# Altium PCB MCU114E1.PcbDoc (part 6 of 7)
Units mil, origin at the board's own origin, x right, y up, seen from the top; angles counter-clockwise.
Board outline 4163.97 x 2322.49 mil, 8 copper layers (Top Layer, GND 2, Signal Layer 3, Power 4, Power 5, Signal Layer 6, GND 7, Bottom), stack 61.2 mil thick; 444 components, 416 nets, 1812 pads, 989 vias.
Unrouted connection lines stored in the file: 3.
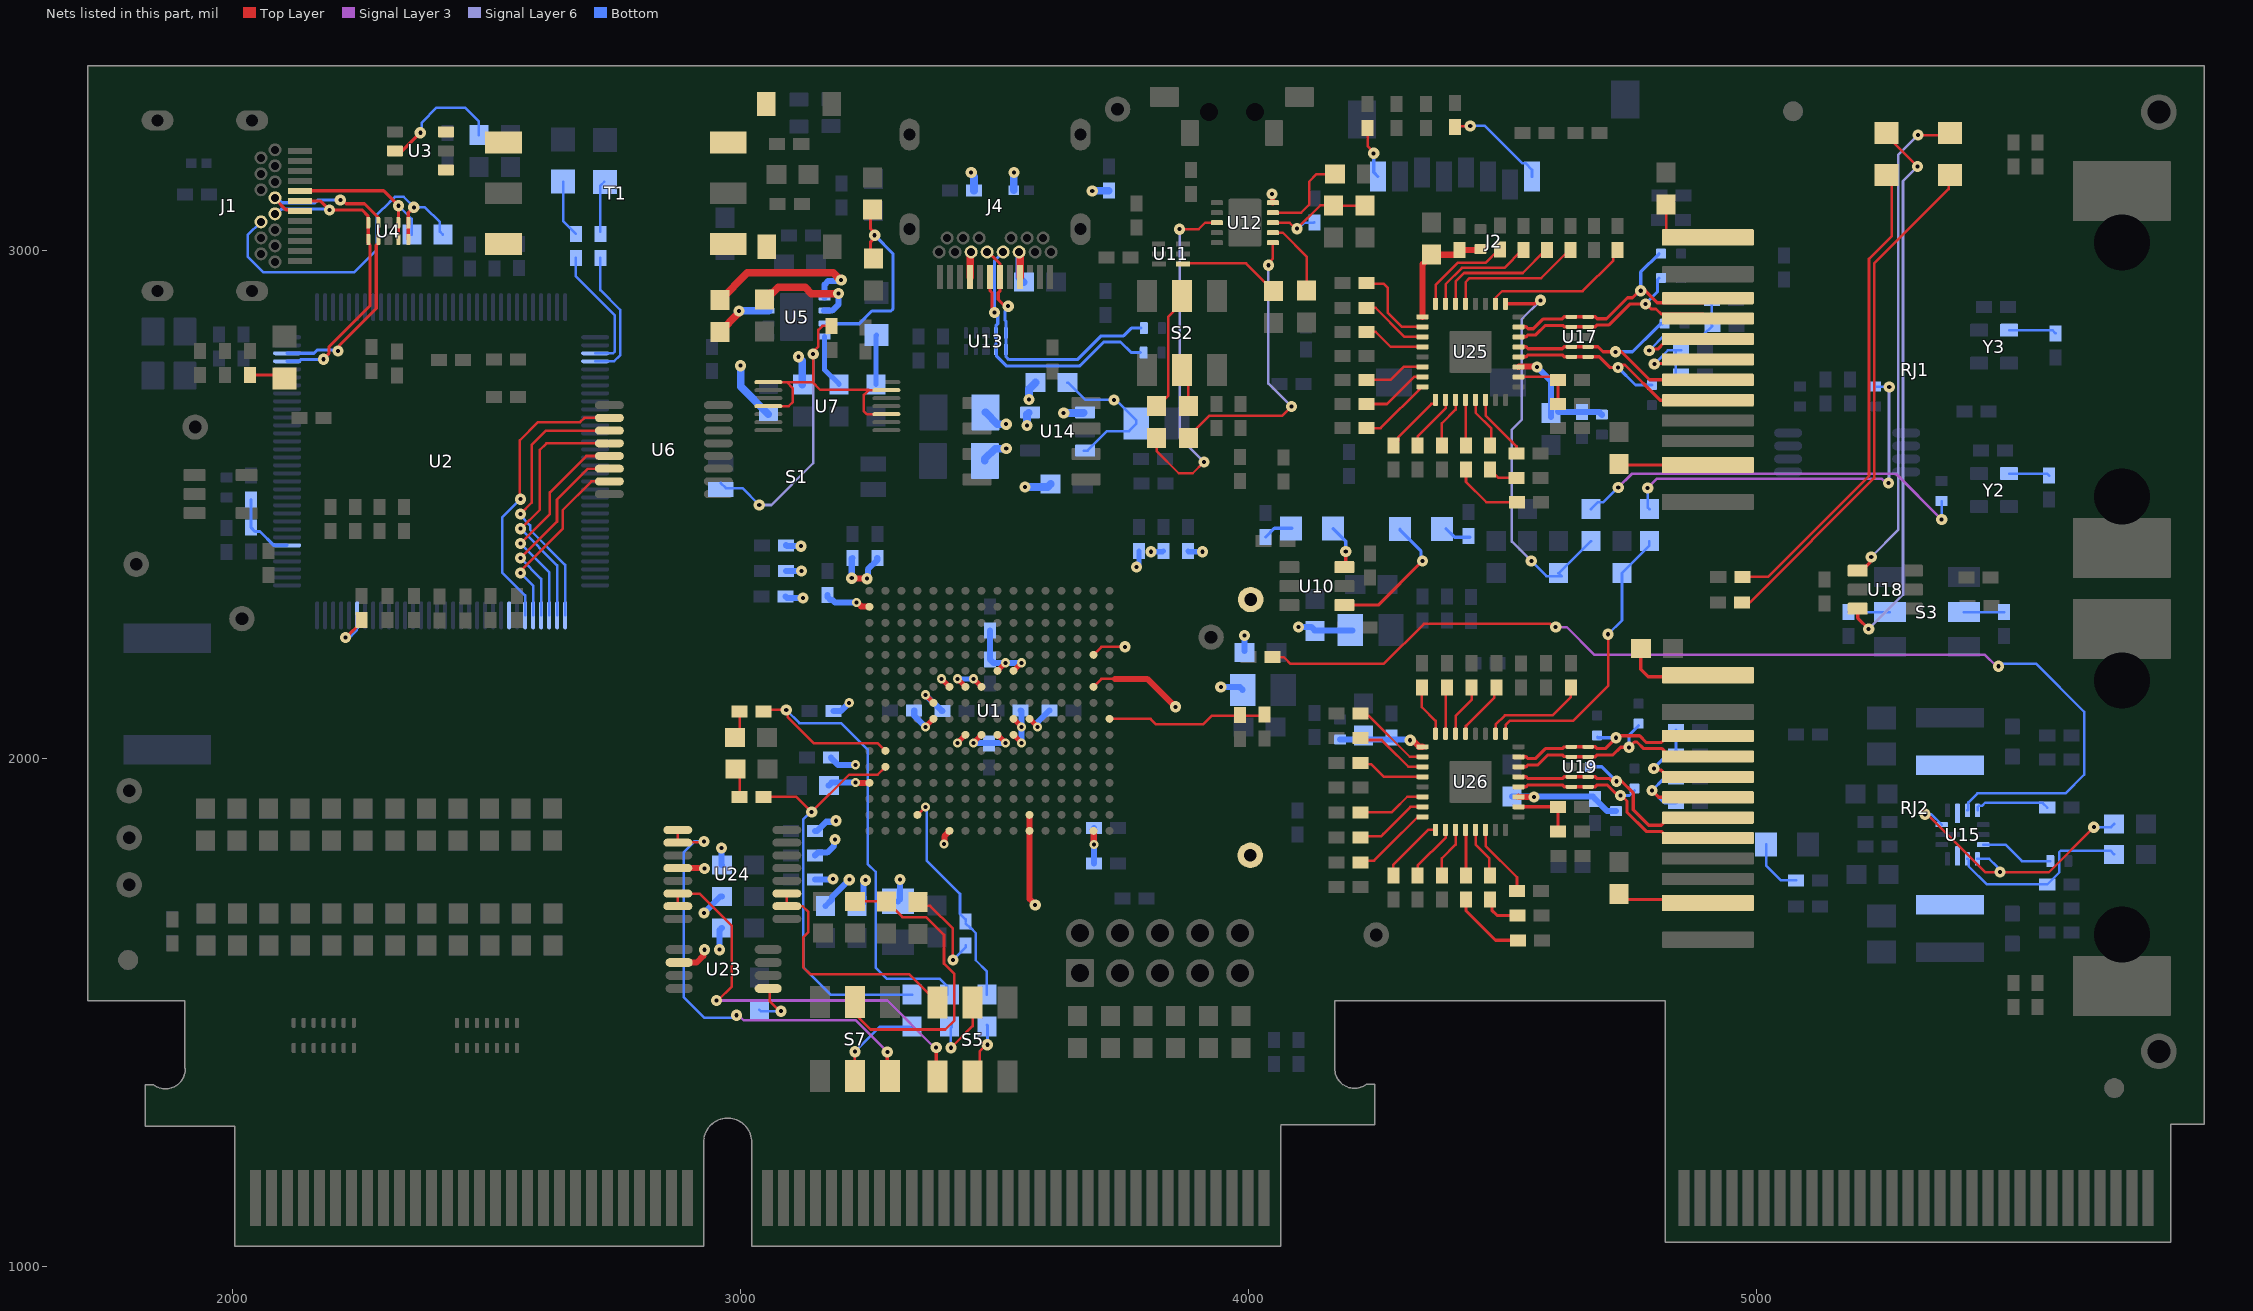
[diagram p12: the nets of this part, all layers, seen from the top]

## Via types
v1: diameter 22, hole 8, Top Layer to Bottom, tented both sides, 818 vias
v2: diameter 18, hole 8, Top Layer to Bottom, tented both sides, 153 vias
v3: diameter 19.68, hole 7.87, Top Layer to Bottom, 18 vias

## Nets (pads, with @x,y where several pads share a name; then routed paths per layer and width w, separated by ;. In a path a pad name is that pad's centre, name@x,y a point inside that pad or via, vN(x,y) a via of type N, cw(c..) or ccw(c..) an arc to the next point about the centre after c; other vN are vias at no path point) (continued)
NetC63_1: C63.1 R198.1 | length 58.3
  Top Layer w5: C63.1@2990.34,1980.27 2998.21,1972.39 R198.1@2998.21,1925.27
NetC87_2: C87.2 C88.2 RJ1.5 | length 321
  Top Layer w6.25: v1(4788,2803) 4791.01,2806.01 4804.85,2806.01 4817.8,2818.96 4896.34,2818.96 RJ1.5@4903.31,2825.92
  Bottom w5: v1(4788,2803) 4819.35,2834.35 4894.89,2834.35 C88.2@4912.38,2851.84 4911.38,2852.84 C87.2@4911.38,2903
NetC89_1: C89.1 C90.1 U25.2 | length 168.8
  Top Layer w5: U25.2@4530.92,2751.47 4601.11,2751.47 C90.1@4608.21,2744.37 ; C90.1@4608.21,2745.27 C90.1@4608.21,2744.37 ; C89.1@4608.81,2697.86 4608.21,2698.47 C90.1@4608.21,2744.37 ; C89.1@4608.81,2703.69 4608.81,2743.77 C90.1@4608.21,2744.37
NetC95_2: C95.2 C96.2 RJ1.6 | length 217.6
  Top Layer w6.25: v1(4798,2777) 4798.9,2777.9 4895.44,2777.9 RJ1.6@4903.31,2785.76
  Bottom w5: v1(4798,2777) 4824.45,2803.45 C96.2@4840.44,2803.45 ; C95.2@4840.44,2758.69 C96.2@4840.44,2803.45 ; C96.2@4850.99,2803.45 C96.2@4840.44,2803.45
NetC97_1: C97.1 C98.1 R131.2 U25.3 | length 235.7
  Top Layer w12: U25.3@4530.92,2771.16 4531.45,2771.69 v1@4567.44,2771.69
  Bottom w12: v1(4567,2771) 4595.08,2742.92 C97.1@4595.08,2672.42 ; C97.1@4608.66,2683.2 4609.66,2682.2 C98.1@4655.66,2682.2 4689.58,2682.2 R131.2@4694.83,2676.95
NetC99_1: C99.1 C100.1 R134.1 U25.17 | length 228.9
  Top Layer w12: U25.17@4341.95,2869.58 4341.95,2972.9 4359.83,2990.79 C99.1@4359.83,2991.77 4409.02,2991.77 4414.83,2997.58 C100.1@4414.83,3000.65 4448.05,3000.65 R134.1@4451.99,3004.58
NetC102_2: C102.2 C104.2 RJ2.5 | length 234.3
  Top Layer w6.25: v1(4797,1981) 4800.01,1977.99 4811.04,1977.99 4824.76,1964.27 RJ2.5@4921.83,1964.27
  Bottom w6.25: v1(4797,1981) 4815.86,1999.86 4831.75,1999.86 C104.2@4840.44,2008.54 C102.2@4840.44,2056.26
NetC105_1: C105.1 C106.1 U26.2 | length 125.7
  Top Layer w6.1: U26.2@4530.92,1905.47 C106.1@4608.81,1905.47 C105.1@4608.81,1857.69
NetC111_2: C111.2 C112.2 RJ2.6 | length 247.7
  Top Layer w6.25: v1(4793.44,1937.5) 4806.83,1924.11 RJ2.6@4921.83,1924.11
  Bottom w6.25: C112.2@4840.44,1913.11 4817.83,1913.11 v1(4793.44,1937.5) 4816.76,1960.83 C111.2@4840.44,1960.83
NetC113_1: C113.1 C114.2 R166.2 U26.3 | length 247.4
  Top Layer w12: U26.3@4530.92,1925.16 4531.4,1924.69 v1(4561.44,1924.69)
  Bottom w12: C113.1@4518,1925.5 4676.95,1925.5 C114.2@4681.65,1920.81 4705.5,1896.95 R166.2@4722.83,1896.95
NetC115_1: C115.1 C116.2 R168.1 U26.17 | length 167.8
  Top Layer w12: v1(4317.67,2036.43) 4320.68,2033.42 4325.22,2033.42 4335.06,2023.58 U26.17@4341.95,2023.58
  Bottom w12: R168.1@4179.99,2037.69 4316.41,2037.69 v1(4317.67,2036.43)
NetC118_1: C118.1 R199.1 | length 190.4
  Top Layer w5: C118.1@3349.59,1718.01 3356.97,1710.63 3372.87,1710.63 3417.83,1665.67 v1(3417.83,1604.27)
  Bottom w5: v1(3417.83,1604.27) 3418.39,1604.27 3442.83,1628.71 R199.1@3442.83,1632.65
NetC119_1: C119.1 R200.1 | length 53.6
  Top Layer w5: C119.1@2990.34,2042.27 2998.21,2050.14 R200.1@2998.21,2092.56
NetC121_1: C121.1 U23.5 | length 104.2
  Top Layer w5: U23.5@3057.19,1552.13 3057.19,1522.91 3076.83,1503.27 v1(3079.83,1503.27)
  Bottom w5: C121.1@3036.87,1506.19 3039.79,1503.27 v1(3079.83,1503.27)
NetC122_1: C122.1 R57.1 S7.5 | length 620.1
  Top Layer w5: R57.1@3225.09,1718.52 R57.1@3225.09,1719.51 3288.1,1719.51 C122.1@3287.59,1719.01 3318.33,1688.27 3365.33,1688.27 3400.33,1653.27 3400.33,1597.02 3420.83,1576.52 3420.83,1485.27 3402.83,1467.27 3256.12,1467.27 3225.59,1497.8 S7.5@3225.59,1521.35
NetD2_2: D2.2 R14.2 | length 70.8
  Top Layer w5: R14.2@2034.87,2755.06 2096.16,2755.06 D2.2@2102.87,2748.35
NetD3_2: D3.2 T1.1
NetD4_2: D4.2 T1.3
NetD5_1: D5.1 U10.6 | length 86.2
  Top Layer w6.25: U10.6@4190.87,2376.69 v1(4190.87,2407.69)
  Bottom w6.25: D5.1@4166.21,2452.69 4190.87,2428.02 v1(4190.87,2407.69)
NetD5_2: D5.2 R34.2 | length 59.3
  Bottom w6.25: R34.2@4032.87,2436.06 4050.49,2453.69 D5.2@4084.87,2453.69
NetD6_1: D6.1 U10.4 | length 271.2
  Top Layer w6.25: U10.4@4188.01,2302.28 4254.85,2302.28 v1(4341.83,2389.27)
  Bottom w6.25: D6.1@4297.49,2452.27 4297.49,2450.3 4338.82,2408.98 4338.82,2392.28 v1(4341.83,2389.27)
NetD6_2: D6.2 R35.2 | length 53.7
  Bottom w6.25: D6.2@4388.21,2452.69 4405.21,2435.69 R35.2@4434.87,2435.69
NetD7_2: D7.2 R21.1 | length 97.3
  Bottom w10: R21.1@3266.55,2736.5 3266.55,2832.24 D7.2@3267.62,2833.31
NetD8_1: D8.1 R8.1 | length 113.1
  Bottom w5: D8.1@2650.87,3135.35 2650.87,3057.91 R8.1@2676.09,3032.69
NetD9_2: D9.2 R94.1 | length 112.9
  Bottom w5: D9.2@5018.1,1831.69 5018.1,1790.02 5047.44,1760.69 R94.1@5077.15,1760.69
NetD11_1: D11.1 U18.6 | length 1090.3
  Top Layer w6.25: U18.6@5198.3,2295.28 5198.3,2276.8 v1(5219.83,2255.27) ; D11.1@5254.83,3231.61 5254.83,3226.27 v1(5315.83,3165.27)
  Signal Layer 6 w5: v1(5219.83,2255.27) 5287.33,2322.77 5287.33,3136.77 v1(5315.83,3165.27)
NetD11_2: D11.2 R137.1 | length 946.9
  Top Layer w5: R137.1@4971.06,2357.69 5021.75,2357.69 5220.44,2556.37 5220.44,2983.44 5265,3028 5265,3138.76 D11.2@5254.83,3148.93
NetD12_1: D12.1 U18.4 | length 975.1
  Top Layer w5: v1(5316.83,3227.27) 5375.68,3227.27 D12.1@5379.44,3231.02
  Top Layer w6.25: U18.4@5198.3,2370.09 5206.18,2370.09 5221.82,2385.73 5221.82,2394.25 v1(5224.83,2397.27)
  Signal Layer 6 w5: v1(5224.83,2397.27) 5278.33,2450.77 5278.33,3188.77 v1(5316.83,3227.27)
NetD12_2: D12.2 R138.2 | length 1019.3
  Top Layer w5: R138.2@4970.49,2307.69 4986.25,2307.69 5230.69,2552.12 5230.69,2974.69 5376.98,3120.98 5376.98,3145.89 D12.2@5379.44,3148.35
NetD13_1: D13.1 R9.1 | length 101.9
  Bottom w5: R9.1@2724.09,3036.63 2724.09,3127.57 D13.1@2731.87,3135.35
NetJ2_1: J2.1 R37.1 | length 201.7
  Top Layer w5: R37.1@4405.83,3242.65 4408.04,3244.85 v1(4435.79,3244.85)
  Bottom w5: v1(4435.79,3244.85) 4436.21,3245.27 4464.56,3245.27 4537.96,3171.87 4544.12,3171.87 4557.37,3158.62 J2.1@4557.37,3145.39
NetJ2_8: J2.8 R43.2 | length 104.1
  Top Layer w5: R43.2@4233.87,3241.06 4233.87,3205.47 4245.83,3193.51 v1(4245.83,3191.27)
  Bottom w6.25: v1(4245.83,3191.27) 4245.83,3153.78 J2.8@4254.22,3145.39
NetL1_1: L1.1 U15.6
NetL2_1: L2.1 U15.12
NetR1_1: R1.1 S1.1 U7.1 U7.4 U7.10 U7.13 | length 1012
  Top Layer w5: U7.4@3054.73,2693.69 3094.87,2693.69 3102.87,2701.69 3102.87,2728.93 3090.87,2740.93 ; U7.1@3054.73,2740.93 3090.87,2740.93 ; 3142.99,2739.56 3142.99,2800.81 3153,2810.81 3153,2843.81 3160.87,2851.69 R1.1@3178.87,2851.69 ; 3252.37,2725.69 3156.87,2725.69 3141.63,2740.93 3090.87,2740.93 ; U7.13@3287.01,2725.18 3252.37,2725.18 3242.87,2715.69 3242.87,2683.69 3248.87,2677.69 U7.10@3288.87,2677.69
  Signal Layer 6 w5: v1(3036.83,2499.27) 3060.73,2499.27 3142.87,2581.41 v1@3142.87,2793.69
  Bottom w5: S1.1@2960.87,2542.69 2971.15,2532.41 3003.69,2532.41 v1(3036.83,2499.27)
  other v1: 3142.99,2796.21
NetR8_2: R8.2 U2.3 | length 255.9
  Bottom w5: R8.2@2676.09,2985.44 2676.09,2949.07 2752.69,2872.48 2752.69,2801.52 2749.02,2797.86 U2.3@2714,2797.86
NetR9_2: R9.2 U2.4 | length 261.5
  Bottom w5: U2.4@2714,2782.11 2751.3,2782.11 2762.87,2793.69 2762.87,2883.48 2724.09,2922.26 R9.2@2724.09,2985.44
NetR10_1: R10.1 R11.2 U2.70 | length 140.6
  Bottom w6.25: R10.1@2036.87,2510.06 R11.2@2036.87,2454.69 2044.4,2447.16 2054.4,2447.16 2081.34,2420.21 2107.39,2420.21 U2.70@2107.7,2419.9
NetR12_2: R12.2 U2.59 | length 105.5
  Top Layer w6.25: v1(2222.83,2238.27) 2223.48,2238.27 2254.09,2268.89 R12.2@2254.09,2272.82
  Bottom w5: v1(2222.83,2238.27) 2226.08,2241.52 2233.65,2241.52 2244.97,2252.84 2244.97,2281.58 U2.59@2245.49,2282.11
NetR18_1: R18.1 U3.5 | length 248.7
  Top Layer w6.25: U3.5@2319.9,3196.07 2334.25,3196.07 v1(2369.87,3231.69)
  Bottom w5: v1(2369.87,3231.69) 2372.89,3234.7 2372.89,3251.86 2402.03,3281 2458.16,3281 2485.09,3254.07 R18.1@2485.09,3226.94
NetR19_1: R19.1 U5.1 | length 327.9
  Top Layer w15: R19.1@2960,2902.5 3013.5,2956 3182.11,2956 3196.11,2942 v1(3198,2942)
  Bottom w12: U5.1@3165.45,2907.38 3165.45,2933.06 3172.48,2940.09 3196.09,2940.09 v1(3198,2942)
NetR24_1: R24.1 R26.2 U5.3 | length 405
  Top Layer w6.25: R24.1@3253.87,3077.19 3255.87,3075.19 3255.87,3042.39 3264,3034.26 3264,3025.74 3255.87,3017.61 R26.2@3255.87,2981.69
  Bottom w6.25: U5.3@3169.9,2856.09 3233.63,2856.09 3258.55,2881 3296.16,2881 3299.82,2884.66 3299.82,2994.18 v1(3264,3030)
NetR25_2: R25.2 U5.4 | length 106.5
  Bottom w10: U5.4@3165.45,2830.61 3165.45,2765.04 3179.31,2751.18 3180.29,2751.18 3193.99,2737.48 R25.2@3193.99,2736.5
NetR27_2: R27.2 U5.2 | length 217.6
  Top Layer w15: R27.2@3050.87,2901.17 3050.87,2908.64 3058,2915.76 3062.02,2915.76 3073.99,2927.74 3126.9,2927.74 3139.37,2915.27 v1(3192.83,2915.27)
  Bottom w12: U5.2@3163.99,2881.68 3180.24,2881.68 3192.83,2894.27 v1(3192.83,2915.27)
NetR33_1: R33.1 S2.2 | length 237.8
  Top Layer w5: R33.1@3820.44,2693.2 3841.81,2714.58 3841.81,2869.81 3851.81,2879.81 3851.81,2893.65 S2.2@3869,2910.83
NetR33_2: R33.2 U12.3 | length 702.6
  Top Layer w5: R33.2@3818.8,2630.9 3818.8,2605.18 3862.21,2561.77 3889.77,2561.77 v1(3912,2584) ; v1(3864,3042) 3901.61,3042 3914.29,3054.69 U12.3@3937.32,3054.69
  Signal Layer 6 w5: v1(3864,3042) 3864,2632 v1(3912,2584)
NetR44_2: R44.2 U11.4 | length 202
  Top Layer w5: U11.4@3870.41,2973.58 3870.41,2974.77 3994.83,2974.77 R44.2@4048.83,2920.76
NetR46_2: R46.2 R48.1 U1.J16 | length 317.2
  Top Layer w5: U1.J16@3726.04,2078.54 3806.73,2078.54 3817.52,2067.75 3910.17,2067.75 3927.33,2084.91 4029.29,2084.91 R46.2@4031,2086.62
NetR49_2: R49.2 U12.9 | length 179.7
  Top Layer w5: U12.9@4047.55,3074.37 4102.83,3074.37 4119,3090.54 4119,3135.77 4133.5,3150.27 R49.2@4169.34,3150.27
NetR52_1: R52.1 U12.6 | length 574.3
  Top Layer w5: R52.1@3881.87,2631.19 3881.87,2634.23 3922.64,2675 4066,2675 v1(4084,2693) ; v1(4039,2971) 4039,2975.6 4047.55,2984.15 U12.6@4047.55,3015.32
  Signal Layer 6 w5: v1(4039,2971) 4038.71,2970.71 4038.71,2738.29 v1(4084,2693)
NetR52_2: R52.2 S2.5 | length 75.6
  Top Layer w5: S2.5@3869,2765.17 3881,2753.17 R52.2@3881,2694.5
NetR53_1: R53.1 U15.4 U15.10 | length 567
  Top Layer w5: v1@5324.44,1890.69 v1(5330.83,1890.69) 5335.31,1890.69 5449.47,1776.53 5574.09,1776.53 v1(5662.83,1865.27)
  Bottom w5: v1(5330.83,1890.69) 5343.27,1890.69 U15.10@5363.59,1870.37 ; U15.4@5433.96,1802.95 5457.01,1802.95 5472.4,1787.56 5472.4,1787.2 5483.07,1776.53 v1@5483.44,1776.53 ; v1(5662.83,1865.27) 5696.61,1865.27 R53.1@5702.94,1871.6
  other v1: 5478,1777
NetR55_2: R55.2 R78.2 R194.1 U12.8 | length 245.2
  Top Layer w5: U12.8@4047.55,3054.69 4080.52,3054.69 4092.21,3043 v1(4095,3043) 4141.06,3089.06 R78.2@4166.72,3089.06 ; R78.2@4168.13,3087.76 R55.2@4231.13,3087.76
  Bottom w5: v1(4095,3043) 4097.79,3043 4109.48,3054.69 4128.31,3054.69 R194.1@4129,3055.38
NetR58_1: R58.1 U25.23 | length 132
  Top Layer w5: R58.1@4232.06,2698.02 4271.77,2698.02 4325.22,2751.47 U25.23@4341.95,2751.47
NetR61_1: R61.1 S5.5 | length 114.4
  Top Layer w5: S5.5@3456.59,1374.68 3470.58,1388.67 3470.58,1424.02 v1@3484.83,1438.27
  Bottom w6.1: R61.1@3484.83,1476.07 3485.58,1475.32 v1(3485.58,1437.27)
NetR61_2: R61.2 R199.2 U1.R4 | length 438.6
  Top Layer w5: U1.R4@3348.09,1889.56 v2(3363.83,1905.31)
  Bottom w5: v2(3363.83,1905.31) 3366.08,1903.06 3366.08,1800.02 3431.83,1734.27 3431.83,1694.83 3442.83,1683.83 R199.2@3442.83,1679.89 ; R199.2@3442.83,1675.95 3452.14,1666.64 3453.15,1666.64 3462.83,1656.96 3462.83,1607.06 3462.83,1603.54 3484.83,1581.54 R61.2@3484.83,1535.76
NetR62_2: R62.2 S3.2 | length 79.2
  Bottom w5: S3.2@5407.27,2288.69 R62.2@5486.44,2288.69
NetR63_2: R63.2 S3.5 | length 81.2
  Bottom w5: R63.2@5180.44,2288.69 S3.5@5261.6,2288.69
NetR69_2: R69.2 Y2.1 | length 80.3
  Bottom w5: Y2.1@5496.13,2561.17 5570.93,2561.17 R69.2@5574.83,2557.27
NetR76_2: R76.2 Y3.1 | length 94.3
  Bottom w5: Y3.1@5496.13,2843.17 5581.56,2843.17 R76.2@5587.83,2836.89
NetR82_2: R82.2 U15.13 | length 2102.6
  Top Layer w5: R82.2@4046.45,2200 4068.91,2200 4082.41,2186.5 4265.5,2186.5 4344.5,2265.5 4592.9,2265.5 4599.4,2259 v1(4604,2259)
  Signal Layer 3 w5: v1(4604,2259) 4625.75,2259 4679.75,2205 4956.35,2205 4956.58,2204.77 4971.08,2204.77 4971.31,2205 5448,2205 5471,2182 v1(5475,2182)
  Bottom w5: U15.13@5414.28,1898.42 5416.05,1900.19 5416.05,1914.31 5433.74,1932 5607,1932 5644.03,1969.03 5644.03,2091.97 5548.69,2187.31 5484.91,2187.31 5479.6,2182 v1(5475,2182)
NetR83_1: R83.1 U25.27 | length 101.1
  Top Layer w5: R83.1@4379.8,2616.31 4379.8,2659.8 4406.91,2686.91 U25.27@4406.91,2706.2
NetR84_1: R84.1 U25.26 | length 112.7
  Top Layer w5: R84.1@4332.12,2616.31 4332.12,2634.47 4387.22,2689.58 U25.26@4387.22,2706.2
NetR86_1: R86.1 U25.25 | length 127.6
  Top Layer w5: R86.1@4284.44,2616.31 4293.75,2625.62 4293.75,2632.41 4359.44,2698.1 4365.12,2698.1 4367.54,2700.53 U25.25@4367.54,2706.2
NetR87_1: R87.1 U25.24 | length 143.5
  Top Layer w5: R87.1@4232.06,2650.69 4259.44,2650.69 4340.54,2731.79 U25.24@4341.95,2731.79
NetR91_1: R91.1 U26.23 | length 147.2
  Top Layer w5: R91.1@4218.95,1847.13 4259.88,1847.13 4264.77,1852.02 4318.22,1905.47 U26.23@4341.95,1905.47
NetR92_1: R92.1 U26.27 | length 101.1
  Top Layer w5: R92.1@4379.8,1770.31 4379.8,1804.05 4406.91,1831.16 U26.27@4406.91,1860.2
NetR97_1: R97.1 U15.3 | length 145.2
  Bottom w5: U15.3@5445.28,1831 5489,1831 5521.31,1798.69 R97.1@5577.1,1798.69
NetR103_1: R103.1 R104.2 U15.5 | length 370.8
  Bottom w5: U15.5@5414.28,1802.95 5416.7,1800.53 5416.7,1788.3 5452.31,1752.69 R103.1@5571.19,1752.69 5594.81,1776.31 5594.81,1816.32 5597.74,1819.25 5695.37,1819.25 R104.2@5702.94,1811.69
NetR109_2: R109.2 U25.10 | length 297.5
  Top Layer w5: U25.10@4485.65,2895.17 4485.65,2907.09 4498.83,2920.27 4656.83,2920.27 4717.36,2980.8 4717.36,2992.18 R109.2@4725.83,3000.65
NetR110_1: R110.1 U26.26 | length 112.6
  Top Layer w5: R110.1@4332.44,1770.31 4332.44,1789.69 4387.22,1844.47 U26.26@4387.22,1860.2
NetR114_2: R114.2 U25.19 | length 133.6
  Top Layer w5: R114.2@4232.06,2887.35 4249.36,2887.35 4306.5,2830.21 U25.19@4341.95,2830.21
NetR115_2: R115.2 U25.18 | length 173.7
  Top Layer w5: R115.2@4232.06,2934.69 4265.44,2934.69 4273.87,2926.25 4273.87,2877.25 4301.22,2849.9 U25.18@4341.95,2849.9
NetR116_2: R116.2 U25.15 | length 216.5
  Top Layer w5: U25.15@4387.22,2895.17 4387.22,2933.66 4419.58,2966.02 4502.86,2966.02 R116.2@4537.49,3000.65
NetR117_2: R117.2 U25.14 | length 246.4
  Top Layer w5: U25.14@4406.91,2895.17 4406.91,2938.85 4423.83,2955.77 4539.18,2955.77 R117.2@4584.06,3000.65
NetR118_2: R118.2 U25.13 | length 272.5
  Top Layer w5: U25.13@4426.59,2895.17 4426.59,2937.56 4434.55,2945.52 4575.49,2945.52 R118.2@4630.62,3000.65
NetR119_2: R119.2 U25.20 | length 122.1
  Top Layer w5: R119.2@4232.06,2840.02 4249.94,2840.02 4279.44,2810.53 U25.20@4341.95,2810.53
NetR120_2: R120.2 U25.22 | length 120.6
  Top Layer w5: R120.2@4232.06,2745.35 4279.1,2745.35 4304.91,2771.16 U25.22@4341.95,2771.16
NetR121_1: R121.1 R123.2 | length 141.3
  Top Layer w5: R121.1@4427.48,2569.06 4427.48,2544.65 4467.44,2504.69 R123.2@4527.81,2504.69
NetR121_2: R121.2 U25.28 | length 90.3
  Top Layer w5: U25.28@4426.59,2706.2 4426.59,2617.19 R121.2@4427.48,2616.31
NetR122_1: R122.1 R124.2 | length 58.4
  Top Layer w5: R122.1@4475.16,2569.06 4491.53,2552.69 R124.2@4526.81,2552.69
NetR122_2: R122.2 U25.29 | length 103.7
  Top Layer w5: U25.29@4446.28,2706.2 4446.28,2680.84 4477.44,2649.69 4477.44,2618.59 R122.2@4475.16,2616.31
NetR125_2: R125.2 U25.30 | length 130.7
  Top Layer w5: U25.30@4465.96,2706.2 4465.96,2675.56 4519.19,2622.34 4526.81,2614.71 R125.2@4526.81,2600.69
NetR126_2: R126.2 U25.16 | length 188.6
  Top Layer w5: U25.16@4367.54,2895.17 4367.54,2931.98 4411.83,2976.27 4466.54,2976.27 R126.2@4490.92,3000.65
NetR132_2: R132.2 RJ1.11 | length 179.1
  Top Layer w6.25: R132.2@4726.64,2592.39 R132.2@4728.94,2594.69 ; R132.2@4728.44,2580.19 4730.73,2577.89 RJ1.11@4903.31,2577.89
NetR135_2: R135.2 RJ1.1 | length 138.4
  Top Layer w5: R135.2@4821.39,3090.33 4821.39,3039.37 4834.83,3025.92 RJ1.1@4903.31,3025.92
NetR143_2: R143.2 U26.10 | length 207.9
  Top Layer w5: U26.10@4485.65,2049.17 4485.65,2067.09 4503.83,2085.27 4597.83,2085.27 4633.83,2121.27 R143.2@4633.83,2140.65
NetR144_1: R144.1 U26.25 | length 132.9
  Top Layer w5: R144.1@4284.44,1770.31 4284.52,1770.39 4284.52,1791.77 4352.95,1860.2 U26.25@4367.54,1860.2
NetR148_2: R148.2 U26.19 | length 144.8
  Top Layer w5: R148.2@4218.95,2036.84 4261.28,2036.84 4272.34,2025.78 4313.91,1984.21 U26.19@4341.95,1984.21
NetR149_2: R149.2 U26.18 | length 156.3
  Top Layer w5: R149.2@4218.95,2084.27 4236.48,2084.27 4316.85,2003.9 U26.18@4341.95,2003.9
NetR150_2: R150.2 U26.15 | length 92.5
  Top Layer w5: U26.15@4387.22,2049.17 4387.22,2138.2 R150.2@4389.66,2140.65
NetR151_1: R151.1 U26.30 | length 145.1
  Top Layer w5: U26.30@4465.96,1859.2 4465.96,1828.6 4527.81,1766.75 R151.1@4527.81,1739.69
NetR152_2: R152.2 U26.14 | length 104.6
  Top Layer w5: U26.14@4406.91,2049.17 4406.91,2084.27 4438.5,2115.86 R152.2@4438.5,2140.65
NetR153_2: R153.2 U26.13 | length 116.6
  Top Layer w5: U26.13@4426.59,2049.17 4427.46,2050.04 4427.46,2064.49 4483.29,2120.33 4483.29,2136.61 R153.2@4487.33,2140.65
NetR154_2: R154.2 U26.20 | length 133.3
  Top Layer w5: R154.2@4218.95,1989.41 4240.59,1989.41 4265.31,1964.69 4341.79,1964.69 U26.20@4341.95,1964.53
NetR155_2: R155.2 U26.22 | length 135.7
  Top Layer w5: R155.2@4218.95,1894.55 4281.3,1894.55 4286.1,1899.35 4311.91,1925.16 U26.22@4341.95,1925.16
NetR156_1: R156.1 R159.2 | length 148.8
  Top Layer w6.25: R156.1@4427.48,1723.06 4427.48,1700.65 4485.44,1642.69 R159.2@4529.81,1642.69
NetR156_2: R156.2 U26.28 | length 90.3
  Top Layer w5: U26.28@4426.59,1860.2 4427.48,1859.31 R156.2@4427.48,1770.31
NetR157_1: R157.1 R160.2 | length 77.3
  Top Layer w6.25: R157.1@4475.16,1723.06 4478.52,1719.7 4478.52,1701.6 4488.44,1691.69 R160.2@4528.81,1691.69
NetR157_2: R157.2 U26.29 | length 101.9
  Top Layer w5: U26.29@4446.28,1860.2 4446.28,1830.84 4473.44,1803.69 4473.44,1772.03 R157.2@4475.16,1770.31
NetR158_2: R158.2 U26.16 | length 102.5
  Top Layer w5: R158.2@4340.83,2140.65 4340.83,2101.29 4367.54,2074.58 U26.16@4367.54,2049.17
NetR167_2: R167.2 RJ2.11 | length 182.3
  Top Layer w6.25: R167.2@4728.44,1734.19 4739.36,1723.27 4896.27,1723.27 RJ2.11@4903.31,1716.24
NetR169_2: R169.2 RJ2.1 | length 152
  Top Layer w6.25: R169.2@4771.34,2217.27 4771.34,2175.76 4785.83,2161.27 4871.57,2161.27 RJ2.1@4874.57,2164.27
NetR171_2: R171.2 U15.14 | length 151.1
  Bottom w5: U15.14@5434.03,1898.49 5434.03,1904.9 5436.38,1907.25 5442.79,1907.25 5448.91,1913.37 5555.01,1913.37 5555.38,1913 5561.88,1913 R171.2@5571.19,1903.69
NetR174_1: R174.1 S7.2 | length 181.2
  Top Layer w5: v1(3225.09,1423.56) 3225.09,1376.18 S7.2@3225.59,1375.68
  Bottom w5: v1(3225.09,1423.56) 3274.3,1472.77 R174.1@3337.83,1472.77
NetR174_2: R174.2 R198.2 U1.M2 | length 839.3
  Top Layer w5: R198.2@3045.62,1925 3110,1925 v1(3140,1895) 3213.53,1968.53 3269.58,1968.53 U1.M2@3285.09,1984.05
  Bottom w5: v1(3140,1895) 3138,1895 3123.09,1880.09 3123.09,1589.8 3177.12,1535.76 R174.2@3337.83,1535.76
NetR187_1: R187.1 S5.2 | length 155.7
  Top Layer w5: v1(3413.83,1431.27) 3456.59,1474.03 S5.2@3456.59,1520.35
  Bottom w5: v1(3413.83,1431.27) 3413.83,1470.36 3415.16,1471.69 R187.1@3415.16,1479.3 ; R187.1@3418.76,1482.6 R187.1@3418.96,1482.39
NetR187_2: R187.2 R200.2 U1.L2 | length 1081.8
  Top Layer w5: R200.2@3045.45,2092.56 3048.89,2096 v1(3090,2096) 3092.46,2093.54 3092.46,2082.3 3143.84,2030.92 3269.72,2030.92 U1.L2@3285.09,2015.55
  Bottom w5: v1(3090,2096) 3115.73,2070.27 3198.08,2070.27 3250.12,2018.23 3250.12,1793.29 3265.83,1777.58 3265.83,1588.91 3287.5,1567.24 3391.83,1567.24 3406.83,1552.24 R187.2@3406.83,1535.76
NetR203_1: R203.1 U26.24 | length 158.7
  Top Layer w5: R203.1@4218.95,1799.7 4246.45,1799.7 4272.42,1825.67 4332.54,1885.79 U26.24@4341.95,1885.79
NetR212_2: R212.2 U12.7 | length 152.8
  Top Layer w5: U12.7@4047.55,3035 4067,3035 4113.87,2988.13 R212.2@4113.87,2921.05
NetS5_3: S5.3 U24.10 U24.11 | length 477.9
  Top Layer w5: U24.11@3091.11,1734.77 U24.10@3091.11,1709.77 3122.33,1709.77 3132.83,1699.27 3132.83,1658.27 3123.2,1648.64 3123.2,1589.69 3136.55,1576.34 3331.7,1576.34 S5.3@3387.7,1520.35
NetS5_6: S5.6 U24.6 U24.7 | length 850.2
  Top Layer w5: U24.7@2876.55,1709.77 U24.6@2876.55,1734.77 2919.33,1734.77 2980.26,1673.84 2982.83,1671.27 2982.83,1551.97 2955.13,1524.27 v1(2952.83,1524.27) ; U24.7@2877.55,1706.77 U24.7@2877.55,1709.77
  Top Layer w6.25: v1(3385,1432) 3385,1377.37 S5.6@3387.7,1374.68
  Signal Layer 3 w5: v1(2952.83,1524.27) 3288.85,1524.27 3381.12,1432 v1(3385,1432)
NetS7_3: S7.3 U24.1 U24.2 | length 910.5
  Top Layer w5: U24.1@2876.55,1859.77 U24.2@2876.55,1834.77 2877.8,1836.02 2926.58,1836.02 v1(2927.83,1837.27)
  Top Layer w6.25: v1(3288.83,1423.27) 3288.83,1381.34 S7.3@3294.49,1375.68
  Signal Layer 3 w5: v1(2991.83,1495.27) 2995.99,1495.27 3006.26,1485 3227.1,1485 v1(3288.83,1423.27)
  Bottom w5: v1(2927.83,1837.27) 2909.38,1837.27 2888,1815.89 2888,1531 2928.76,1490.24 2982.2,1490.24 2987.23,1495.27 v1(2991.83,1495.27)
NetT1_4: T1.4 U3.3
NetT1_6: T1.6 U3.1
PHY0_25MHZ_CLK: R60.2 R67.2 | length 792.5
  Signal Layer 3 w5.2: v1(4727,2534) 4753.77,2560.77 5273.35,2560.77 v1(5363.44,2470.69)
  Bottom w5.2: R60.2@4673.44,2491.17 4687.12,2504.85 4697.85,2504.85 v1(4727,2534) ; v1(5363.44,2470.69) R67.2@5363.44,2507
PHY0_CLK: R59.2 R60.1 U25.9 | length 793.8
  Top Layer w6.25: U25.9@4505.33,2895.17 4562.91,2895.17 4569.74,2902 v1(4574,2902)
  Signal Layer 6 w5: v1(4556,2389) 4517.71,2427.29 4517.71,2647.78 4536.76,2666.83 4536.76,2857.52 4536.76,2864.76 v1(4574,2902)
  Bottom w5: v1(4556,2389) 4585.73,2359.27 4615.35,2359.27 R59.2@4609.44,2365.18 4610.44,2365.18 R60.1@4673.44,2428.17
PHY0_RD_N: C93.1 RJ1.8 U17.5 U17.6 U25.4 | length 495.2
  Top Layer w6.2: U25.4@4530.92,2790.84 4545.73,2790.84 4549.58,2794.69 4616.9,2794.69 4620.74,2790.84 U17.5@4634.86,2790.84 U17.6@4667.74,2790.84 4689.56,2790.84 4710.42,2769.98 v1(4726.44,2769.98) ; v1@4726.12,2773 4727.8,2774.69 4740.42,2774.69 4809.65,2705.45 RJ1.8@4903.31,2705.45
  Bottom w6.2: v1(4726.44,2769.98) 4760.9,2735.52 C93.1@4793.45,2735.52
PHY0_RD_P: C94.1 RJ1.7 U17.4 U17.7 U25.5 | length 518.3
  Top Layer w6.2: U25.5@4530.92,2810.53 4545.73,2810.53 4549.58,2806.69 4616.9,2806.69 4620.74,2810.53 U17.4@4634.86,2810.53 U17.7@4667.74,2810.53 4687.13,2810.53 4696.97,2800.69 v1(4721.44,2800.69) 4733.49,2800.69 4788.57,2745.61 RJ1.7@4903.31,2745.61
  Bottom w6.2: v1(4721.44,2800.69) 4755.13,2800.69 4801.73,2847.29 4810.44,2856 C94.1@4814.38,2856
PHY0_TD_N: C91.1 RJ1.4 U17.2 U17.9 U25.6 | length 475.7
  Top Layer w6.2: U25.6@4530.92,2830.21 4545.83,2830.21 4549.58,2833.96 4565.05,2833.96 4583.9,2852.8 4617.74,2852.8 4620.64,2849.9 U17.2@4634.86,2849.9 U17.9@4667.74,2849.9 4681.96,2849.9 4685.7,2853.64 4709.05,2853.64 4750.37,2894.95 v1(4780.55,2894.95) 4782.13,2894.95 4792.09,2885 4801.33,2885 4811.34,2874.99 4894.4,2874.99 RJ1.4@4903.31,2866.08
  Bottom w6.2: v1(4780.55,2894.95) 4804.28,2918.68 4804.28,2942.9 C91.1@4807.38,2946
PHY0_TD_P: C92.1 RJ1.3 U17.1 U17.10 U25.7 | length 518.4
  Top Layer w6.2: U25.7@4530.92,2849.9 4545.83,2849.9 4549.58,2846.16 4560,2846.16 4578.84,2865 4616.06,2865 4620.64,2869.58 U17.1@4634.86,2869.58 U17.10@4667.74,2869.58 4681.96,2869.58 4685.7,2865.84 4704,2865.84 4745.31,2907.15 4755,2907.15 4768.69,2920.84 v1(4771.36,2920.84) 4780.27,2920.84 4792.27,2908.83 4803.78,2897.33 4894.4,2897.33 RJ1.3@4903.31,2906.24
  Bottom w6.2: v1@4764.89,2914.7 v1@4771.2,2921.01 ; v1(4771.36,2920.84) 4771.36,2957.99 C92.1@4807.38,2994
PHY1_25MHZ_CLK: R66.2 R68.2 | length 746.3
  Signal Layer 3 w5.2: v1(4785,2533) 4802.77,2550.77 5245.73,2550.77 5254.23,2542.27 v1(5258.83,2542.27)
  Signal Layer 6 w5.2: v1(5258.83,2542.27) 5259.83,2543.27 5259.83,2731.27 v1(5260.33,2731.77)
  Bottom w5.2: v1(4785,2533) 4785,2494.6 R66.2@4788.44,2491.17 ; R68.2@5232.44,2732.53 5233.19,2731.77 v1(5260.33,2731.77)
PHY1_CLK: R64.2 R66.1 U26.9 | length 569.1
  Top Layer w5: U26.9@4505.33,2049.17 4505.33,2066.11 4514.22,2075 4638.56,2075 4707,2143.44 v1(4707,2245)
  Bottom w5: v1(4707,2245) 4734.44,2272.44 R64.2@4734.44,2365.18 4788.44,2419.18 R66.1@4788.44,2428.17
PHY1_RD_N: C109.1 RJ2.8 U19.5 U19.6 U26.4 | length 465.4
  Top Layer w6.2: U26.4@4530.92,1944.84 4545.83,1944.84 4549.58,1948.59 4616.9,1948.59 4620.64,1944.84 U19.5@4634.86,1944.84 U19.6@4667.74,1944.84 4681.96,1944.84 4685.7,1948.59 4704.94,1948.59 4725.84,1927.69 v1(4731.44,1927.69) 4733.5,1927.69 4744.25,1916.93 4744.25,1894.69 4781.95,1857 4812.22,1857 4815.85,1853.37 4815.85,1852.7 4824.76,1843.8 RJ2.8@4903.31,1843.8
  Bottom w6.2: v1(4731.44,1927.69) 4749.31,1927.69 C109.1@4759,1937.38
PHY1_RD_P: C110.1 RJ2.7 U19.4 U19.7 U26.5 | length 502
  Top Layer w6.2: U26.5@4530.92,1964.53 4545.83,1964.53 4549.58,1960.79 4616.9,1960.79 4620.64,1964.53 U19.4@4634.86,1964.53 U19.7@4667.74,1964.53 4681.96,1964.53 4685.7,1960.79 4709.99,1960.79 4715.09,1955.69 v1(4723.44,1955.69) 4733.51,1955.69 4756.45,1932.74 4756.45,1899.75 4787,1869.2 4812.22,1869.2 4815.85,1872.83 4815.85,1875.05 4824.76,1883.95 RJ2.7@4903.31,1883.95
  Bottom w6.2: C110.1@4674.92,1984.21 4694.91,1984.21 v1(4723.44,1955.69)
PHY1_TD_N: C107.1 RJ2.4 U19.2 U19.9 U26.6 | length 429.1
  Top Layer w6.2: U26.6@4530.92,1984.21 4545.83,1984.21 4549.58,1987.96 4569.05,1987.96 4588.74,2007.64 4617.11,2007.64 4620.53,2004.22 4634.54,2004.22 U19.2@4634.86,2003.9 U19.9@4667.74,2003.9 4681.96,2003.9 4685.7,2007.64 4716.64,2007.64 4731.64,2022.64 4747.95,2022.64 v1(4748.14,2022.44) 4758.7,2033 4764,2033 4777.2,2019.8 4813.42,2019.8 RJ2.4@4817.85,2015.37 ; RJ2.4@4842.4,2004.43 RJ2.4@4903.31,2004.43
  Bottom w6.2: v1(4748.14,2022.44) 4748.14,2046.36 C107.1@4766.92,2065.15
PHY1_TD_P: C108.1 RJ2.3 U19.1 U19.10 U26.7 | length 355.1
  Top Layer w6.2: U26.7@4530.92,2003.9 4545.83,2003.9 4549.58,2000.16 4564,2000.16 4583.69,2019.84 4617.11,2019.84 4620.53,2023.26 4634.54,2023.26 U19.1@4634.86,2023.58 U19.10@4667.74,2023.58 4681.96,2023.58 4685.7,2019.84 4701.4,2019.84 v1(4722.83,2041.27) 4726.76,2045.2 4769.05,2045.2 4782.25,2032 4812.22,2032 4815.85,2035.64 4817.22,2037.05 RJ2.3@4817.85,2037.05
  Bottom w6.2: C108.1@4686.08,2042.65 4687.46,2041.27 v1(4722.83,2041.27)
POWER_SWITCH_OUT: C26.1 R19.2 R20.1 U5.7 | length 291.2
  Top Layer w15: R19.2@2960,2839.5 2960,2840.49 2995.66,2876.15 2995.66,2879.66 v1(2997,2881)
  Bottom w15: v1(2997,2881) 2997.39,2881.39 3054.82,2881.39 U5.7@3055.22,2881.79 ; v1(2999.91,2773.43) 3000.23,2773.11 3000.23,2732.43 R20.1@3054.73,2677.94 ; v1(3114,2791) 3121.57,2783.43 C26.1@3121.57,2736.5
USB-PFLT: R85.1 R90.1 U14.3 | length 298.6
  Bottom w5: R90.1@3643.39,2740.22 3644.37,2740.22 3678.59,2706 3738.6,2706 3778.83,2665.77 R85.1@3778.83,2659.27 3764.33,2644.77 3721.37,2644.77 3682.88,2606.28 U14.3@3675.01,2606.28
  other v1: 3735,2706
USB_5V0: C46.1 C47.1 R90.2 R93.2 U14.5 | length 202.9
  Bottom w15: C47.1@3480.84,2586.01 3480.84,2590.21 3500.9,2610.27 v1(3522.83,2610.27) ; C46.1@3482.05,2681.69 3505.45,2658.29 v1(3522.69,2658.29) ; v1(3563.55,2655.99) 3563.55,2677.9 U14.5@3566.74,2681.09 ; v1(3567.7,2706.94) 3567.7,2727.53 R90.2@3580.4,2740.22 ; v1(3692,3117) 3692.32,3117.32 3724.51,3117.32 R93.2@3724.83,3117.65
USB_D_N: J4.A7 J4.B7 R81.1 U13.2 U13.9 | length 598.1
  Top Layer w6.1: J4.A7@3491.16,2947.46 3491.16,2920.79 3494.95,2917 v1@3494.95,2887.17
  Bottom w6.1: J4.B7@3516.75,2997.07 3499.83,2980.15 v1(3499.83,2878.23) 3506.16,2871.89 3506.16,2855.96 3502.37,2852.17 U13.9@3502.37,2838 U13.2@3502.37,2805.13 3503.26,2804.24 3503.26,2792.74 3522.91,2773.09 3667.76,2773.09 3671.31,2776.63 3714.67,2820 3747.77,2820 3768.58,2799.19 R81.1@3787.38,2799.19
USB_D_P: J4.A6 J4.B6 R80.1 U13.1 U13.10 | length 528.5
  Top Layer w6.1: J4.B6@3485.25,2997.07 3487.27,2997.07 3510.84,2973.5 J4.A6@3510.84,2947.46 3510.84,2920.79 3507.05,2917 3507.05,2903.77 3520.37,2890.45 v1(3526.67,2890.45)
  Bottom w6.1: v1(3526.67,2890.45) 3526.67,2886.14 3520.12,2879.59 3520.12,2863.35 3522.06,2861.42 U13.10@3522.06,2838 U13.1@3522.06,2805.13 3522.34,2804.84 3522.34,2790.77 3527.92,2785.19 3662.75,2785.19 3709.66,2832.1 3753.87,2832.1 3768.96,2847.19 R80.1@3787.76,2847.19
VBUS_5V0: C44.1 C45.1 J4.A4 J4.A9 J4.B4 J4.B9 R77.2 R79.2 U14.1 | length 329
  Top Layer w15: J4.A9@3451.79,2947.46 3451.79,2995.1 J4.B4@3453.76,2997.07 ; J4.B9@3548.24,2997.07 3550.21,2995.1 J4.A4@3550.21,2947.46
  Bottom w15: v1(3453.83,3153.27) 3453.83,3150.56 3459.4,3144.99 R77.2@3459.4,3117.69 ; C44.1@3537.87,3118.69 v1@3537.85,3153.25 ; J4.B9@3548.24,2997.07 3548.24,2946.9 R79.2@3557.32,2937.82 ; v1(3559.71,2534.66) 3604.36,2534.66 C45.1@3610.38,2540.69 ; v1(3635.83,2680.27) 3674.19,2680.27 U14.1@3675.01,2681.09
  other v1: 3537.83,3153.27
VDD_1V2: C55.1 C56.1 C57.1 C58.1 C59.1 C60.1 C61.1 C85.1 L5.2 TP13.1 U1.F9 U1.F10 U1.G6 U1.J11 U1.K8 U1.K9 U12.10 | length 567.9
  Top Layer w10: v2(3395.33,2157.28) U1.G6@3411.08,2141.53 ; v2(3458.32,2031.29) U1.K8@3474.07,2047.04 ; U1.K9@3505.57,2047.04 v2(3521.31,2031.29) ; U1.F9@3505.57,2173.03 v2(3521.31,2188.77) ; U1.F10@3537.06,2173.03 v2(3552.81,2188.77) ; U1.J11@3568.56,2078.54 v2(3584.31,2062.79) ; v1(4045.83,3111.27) 4046.69,3110.41 4046.69,3094.13 4046.77,3094.06 U12.10@4047.55,3094.06
  Bottom w10: v1@3784.07,2383.34 C57.1@3784.07,2408.93 ; v1(3807.83,2407.27) 3830.41,2407.27 C59.1@3832.07,2408.93 ; C60.1@3880.07,2408.93 3881.73,2407.27 v1(3908.83,2407.27)
  Bottom w12: v2(3458.32,2031.29) v2(3521.31,2031.29) ; C55.1@3491.09,2252.44 3490.54,2251.89 C56.1@3490.54,2195.65 3497.42,2188.77 v2(3521.31,2188.77) v2(3552.81,2188.77) ; v2(3584.31,2062.79) 3584.31,2071.41 C58.1@3607.92,2095.03 ; v1(4097.83,2259.27) 4123.29,2259.27 4129.87,2252.69 L5.2@4203.87,2252.69
  other v1: 3778.83,2377.27
VDDA_3V3: C32.1 C33.1 C62.1 C67.1 C120.1 C124.1 L4.2 U1.N1 U1.T6 U23.2 U24.4 | length 528.2
  Top Layer w12: U24.4@2876.55,1784.77 v1@2928.33,1784.77 ; U23.2@2879.23,1599.06 2913.63,1599.06 2926.96,1612.4 2926.96,1622.25 v1(2928.87,1624.16) ; v2(3226.54,1953.03) 3227.02,1952.55 U1.N1@3253.6,1952.55 ; v2(3400.09,1832.07) 3401.24,1833.21 3401.24,1847.22 3411.08,1857.05 U1.T6@3411.08,1858.07
  Bottom w12: v1(2927.83,1696.27) 2960.61,1729.04 C62.1@2963.1,1729.04 ; v1(2958.83,1624.27) 2958.83,1662.94 C124.1@2963.1,1667.21 ; v1(2962.83,1824.27) 2962.83,1791.08 C120.1@2963.1,1790.81 ; C33.1@3167.17,1710.23 3179.87,1722.93 3179.87,1727.87 v1(3214,1762) ; C32.1@3173.59,1947.07 3179.56,1953.03 v2(3226.54,1953.03) ; C67.1@3235.83,1710.76 3241.87,1716.8 3241.87,1754.16 3246,1758.29 v1(3246,1761) ; L4.2@3309.83,1719.27 3313.83,1723.27 v1(3313.83,1762.27)
  other v1: 2928.83,1784.27
VDDIO_3V3: C65.1 C68.1 C69.1 C70.1 C71.1 C72.1 C73.1 C74.1 C75.1 C76.1 C77.1 C78.1 C79.1 C80.1 C81.1 C82.1 C83.1 L3.2 TP12.1 U1.B1 U1.E15 U1.G7 U1.G8 U1.G15 U1.H5 U1.J5 U1.J10 U1.K7 U1.K10 U1.R11 U1.T11 U1.T15 | length 1500.9
  Top Layer w5: U1.G15@3694.54,2141.53 3710.29,2157.28 3736.98,2157.28 ; U1.E15@3694.54,2204.52 3710.29,2220.27 v1(3756.69,2220.27)
  Top Layer w6.1: U1.T15@3694.54,1858.07 U1.T15@3695.07,1857.54 ; v2@3695.07,1832.09 v2(3695.59,1831.56)
  Top Layer w10: v2(3363.83,2062.79) U1.J5@3379.58,2078.54 ; v2(3363.83,2125.78) U1.H5@3379.58,2110.03 ; v2(3426.83,2031.29) U1.K7@3442.57,2047.04 ; v2(3426.83,2157.28) U1.G7@3442.57,2141.53 ; v2(3458.32,2157.28) U1.G8@3474.07,2141.53 ; U1.K10@3537.06,2047.04 v2(3552.81,2031.29) ; U1.J10@3537.06,2078.54 v2(3552.81,2062.79)
  Top Layer w12: v1(3218.83,2355.27) 3219.83,2354.27 v1(3248.83,2354.27) ; v2(3228.01,2307.27) 3229.63,2307.27 3237.17,2299.73 3252.88,2299.73 U1.B1@3253.6,2299.01 ; U1.R11@3568.56,1889.56 3568.56,1724.3 3579.83,1713.03 v1(3579.83,1712.27) ; v2@3695.07,1832.09 U1.T15@3695.07,1857.54 ; 3736.98,2157.28 3800,2157.28 3855,2102.28 v1@3855,2100
  Bottom w10: v2(3426.83,2157.28) v2(3458.32,2157.28)
  Bottom w12: C76.1@3088.72,2319.07 3091.51,2316.27 v1(3122.83,2316.27) ; C72.1@3089.72,2369.07 3119.63,2369.07 v1(3119.83,2369.27) ; C74.1@3089.72,2420.07 3091.51,2418.27 v1(3118.83,2418.27) ; C68.1@3146.72,1762.07 3147.32,1762.67 3181.23,1762.67 v1(3181.83,1763.27) ; C75.1@3146.72,1810.07 3152.04,1815.39 3170.41,1815.39 3184.09,1829.06 3184.09,1839.09 v1(3186,1841) ; C83.1@3146.72,1858.07 3150.65,1858.07 3168.67,1876.09 3186.09,1876.09 v1(3188,1878) ; C73.1@3171.09,2322.44 3171.09,2318.51 3176.91,2312.7 3180.84,2312.7 3186.27,2307.27 v2(3228.01,2307.27) ; C79.1@3177.72,2002.07 3191.72,1988.07 v2(3226.09,1988.07) ; C69.1@3182.72,2094.07 3197.86,2094.07 v2(3213.83,2110.03) ; v1(3218.83,2355.27) 3218.83,2393.69 C81.1@3220.07,2394.93 ; v1(3248.83,2354.27) 3250.74,2356.18 3250.74,2372.67 3269.07,2391 C80.1@3269.07,2394.93 ; C77.1@3341.72,2095.07 3341.72,2084.91 v2(3363.83,2062.79) ; v2(3363.83,2125.78) 3395.59,2094.03 C71.1@3396.92,2094.03 C71.1@3395.88,2095.07 ; C70.1@3551.17,2095.03 3552.81,2093.38 v2(3552.81,2062.79) v2(3552.81,2031.29) ; C78.1@3695.47,1794.07 C82.1@3695.47,1864.07 ; v1(3945,2141) 3982.56,2141 L3.2@3987.87,2135.69 ; C65.1@3991.38,2211.69 3991.83,2212.14 v1(3991.83,2242.27)
  other v1: 3855.95,2102.21
XDS_CC1: J1.A5 R16.2 U4.4 U4.7 | length 339.5
  Top Layer w6.25: J1.A5@2133.54,3117.53 2297.63,3117.53 v1(2327.09,3088.07) 2326.81,3087.78 2326.81,3054.98 U4.7@2326.53,3054.7 U4.4@2326.53,3021.82
  Bottom w5: v1(2327.09,3088.07) 2353.09,3062.07 R16.2@2353.09,3031.56
XDS_CC2: J1.B5 R17.1 U4.5 U4.6 | length 689.6
  Top Layer w6.25: U4.5@2346.22,3021.82 U4.6@2346.22,3054.7 2346.22,3074.19 v1(2357.09,3085.07)
  Bottom w5: J1.B5@2056.37,3056.5 2030,3030.13 2030,2988 2061,2957 2226.95,2957 2227,2957.05 2239.62,2957.05 2283.83,3001.27 2283.83,3069.55 2311.04,3096.76 ; 2309.59,3095.31 2311.04,3096.76 ; R17.1@2414.09,3031.56 2408.28,3037.38 2408.28,3055.82 2379.03,3085.07 v1(2357.09,3085.07) 2357.09,3085.79 2337.32,3105.57 2319.85,3105.57 2311.04,3096.76
XDS_D_N: J1.A7 J1.B7 U2.94 U4.2 U4.9 | length 684.5
  Top Layer w6.1: J1.B7@2083.93,3103.75 2083.93,3101.73 2105.39,3080.28 2131.42,3080.28 J1.A7@2133.54,3078.16 ; v1(2208.09,2802.07) 2211.14,2805.11 2211.14,2814.02 2283.11,2886 2283.11,3010.58 2287.16,3014.64 U4.2@2287.16,3021.82 U4.9@2287.16,3054.7 2286.27,3055.58 2286.27,3065.84 2260.01,3092.1 2224.18,3092.1 2222.93,3093.35 2222.73,3093.35 2216.83,3099.25 v1(2212.53,3099.25)
  Bottom w6.1: J1.B7@2083.93,3103.75 2087.55,3103.75 2097.25,3094.05 2162.63,3094.05 2167.83,3099.25 v1(2212.53,3099.25) ; U2.94@2107.7,2797.86 2160.74,2797.86 2167,2804.12 2206.04,2804.12 v1(2208.09,2802.07)
XDS_D_P: J1.A6 J1.B6 U2.93 U4.1 U4.10 | length 652.4
  Top Layer w6.1: J1.A6@2133.54,3097.84 2173.16,3097.84 v1(2191,3080) 2255,3080 2266.59,3068.41 2266.59,3055.58 U4.10@2267.48,3054.7 U4.1@2267.48,3021.82 2267.48,3014.64 2271.01,3011.1 2271.01,2891.01 2190.04,2810.04 2190.04,2797.02 v1(2179.09,2786.07)
  Bottom w6.1: J1.B6@2083.93,3072.25 2087.55,3072.25 2097.25,3081.95 2189.05,3081.95 v1(2191,3080) ; U2.93@2107.7,2782.11 2131.8,2782.11 2135.45,2785.76 2178.78,2785.76 v1(2179.09,2786.07)
XDS_RESET_OUT: U2.40
XDS_RXD: U2.33 U6.3 | length 548.8
  Top Layer w5: v1(2566.87,2481.69) 2588.87,2503.69 2588.87,2617.69 2616.87,2645.69 U6.3@2741.87,2645.69 U6.3@2744.87,2645.69
  Bottom w5: v1(2566.87,2481.69) 2566.87,2478.23 2586,2459.1 2586,2450.56 2654.94,2381.62 U2.33@2654.94,2282.11
XDS_TCK_SWDCLK: U2.35 U6.5 | length 436.1
  Top Layer w5: v1(2566.87,2423.69) 2624.83,2481.64 2624.83,2523.98 2696.53,2595.69 U6.5@2741.87,2595.69
  Bottom w5: v1(2566.87,2423.69) 2623.44,2367.11 U2.35@2623.44,2282.11
XDS_TDI: U2.38 U6.2 | length 571.5
  Top Layer w5: v1@2565.87,2511.69 2565.87,2626.69 2601.46,2662.27 2684.46,2662.27 2692.87,2670.69 U6.2@2741.87,2670.69
  Bottom w5: v1(2566.87,2510.69) 2530.87,2474.69 2530.87,2366.69 2576.2,2321.36 U2.38@2576.2,2282.11
XDS_TDO_SWO: U2.37 U6.7 | length 367.2
  Top Layer w5: v1(2566.87,2365.69) 2566.87,2369.14 2649.83,2452.1 2649.83,2488.98 2706.53,2545.69 U6.7@2741.87,2545.69
  Bottom w5: v1(2566.87,2365.69) 2591.95,2340.61 U2.37@2591.95,2282.11
XDS_TMS_SWDIO: U2.36 U6.6 | length 402.8
  Top Layer w5: v1(2566.87,2394.69) 2638.83,2466.64 2638.83,2509.98 2699.53,2570.69 U6.6@2741.87,2570.69
  Bottom w5: v1(2566.87,2394.69) 2607.7,2353.86 U2.36@2607.7,2282.11
XDS_TXD: U2.34 U6.4 | length 514.7
  Top Layer w5: v1@2566.87,2451.69 2604.87,2489.69 2604.87,2607.69 2617.87,2620.69 U6.4@2741.87,2620.69
  Bottom w5: v1(2566.87,2452.69) 2639.19,2380.37 U2.34@2639.19,2282.11
pads on no net: B1.7 EC1.4 EC1.13 EC1.16 EC1.29 EC1.32 EC1.41 EC1.43 EC1.44 EC1.66 EC1.113 EC1.114 EC1.115 EC1.116 EC1.117 EC2.136 EC2.171 EC2.172 EC2.173 EC2.174 EC2.175 EC2.176 EC2.177 FID1.1 FID2.1 FID3.1 FID4.1 FID5.1 FID6.1 J1.A2 J1.A3 J1.A8 J1.A10 J1.A11 J1.B2 J1.B3 J1.B8 J1.B10 J1.B11 J3.9 J4.A2 J4.A3 J4.A8 J4.A10 J4.A11 J4.B2 J4.B3 J4.B8 J4.B10 J4.B11 LBL1.0 RJ1.9 RJ1.ALIGN1 RJ1.ALIGN2 RJ2.9 RJ2.ALIGN1 RJ2.ALIGN2 S4. U1.G16 U1.H1 U1.J1 U1.J2 U1.K1 U1.K3 U1.K4 U1.L6 U1.N5 U1.N6 U1.N8 U1.P4 U1.P5 U1.P6 U1.P8 U1.R5 U1.R7 U2.1 U2.2 U2.5 U2.6 U2.11 U2.12 U2.13 U2.14 U2.15 U2.18 U2.19 U2.20 U2.21 U2.22 U2.23 U2.24 U2.25 U2.27 U2.29 U2.30 U2.31 U2.32 U2.41 U2.42 U2.43 U2.44 U2.45 U2.46 U2.49 U2.50 U2.53 U2.54 U2.56 U2.57 U2.65 U2.67 U2.71 U2.72 U2.73 U2.74 U2.75 U2.76 U2.77 U2.78 U2.81 U2.82 U2.83 U2.84 U2.85 U2.86 U2.91 U2.92 U2.95 U2.102 U2.103 U2.104 U2.105 U2.106 U2.107 U2.108 U2.109 U2.110 U2.111 U2.112 U2.116 U2.117 U2.118 U2.119 U2.120 U2.121 U2.123 U2.124 U2.125 U2.126 U2.127 U2.128 U4.3@2306.85,3021.82 U4.8@2306.85,3054.7 U5.9@3110.34,2844.19 U5.9@3110.34,2893.8 U11.6 U13.3@3482.69,2805.13 U13.8@3482.69,2838 U17.3@4634.86,2830.21 U17.8@4667.74,2830.21 U19.3@4634.86,1984.21 U19.8@4667.74,1984.21 U23.1 U23.3 U23.7 U23.8 U24.8 U24.9 U24.16 U25.1 U25.8 U25.33@4413.99,2778.24 U25.33@4413.99,2823.13 U25.33@4458.88,2778.24 U25.33@4458.88,2823.13 U26.1 U26.8 U26.33@4413.99,1932.24 U26.33@4413.99,1977.13 U26.33@4458.88,1932.24 U26.33@4458.88,1977.13
copper on no net: | length 141.1
  Bottom w5: 5018.1,1920.69 5033.82,1936.41 5033.82,1948.88 5059.98,1975.03 5098.81,1975.03 5120.46,1996.69

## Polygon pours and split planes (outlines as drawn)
EMU_USB_5V0 on Top Layer "TOP_LAYER_EMU_USB_5V0_P240" (solid, remove dead copper, pour order 240): 1746,2456 1748,2454 1963,2454 1963,2714 1970,2721 2000,2721 2011,2732 2011,2774 2003,2782 1904,2782 1900,2786 1900,3015 1899,3015 1879,3035 1745,3035
POWER_SWITCH_OUT on Top Layer "TOP_LAYER_POWER_SWITCH_OUT_P216" (solid, remove dead copper, pour order 216): 2924.45,2984 3007.87,2984 3007.87,2816.64 3178.03,2816.64 3178.03,2728.52 2924.45,2728.52
NetT1_4 on Top Layer "TOP_LAYER_NETT1_4_P165" (solid, remove dead copper, pour order 165): 2402,3254 2573,3254 2589,3238 2589,3188 2578,3177 2485,3177 2449,3213 2448.37,3212.37 2399.63,3212.37 2392,3220 2392,3244
NetT1_6 on Top Layer "TOP_LAYER_NETT1_6_P166" (solid, remove dead copper, pour order 166): 2396,3180 2452,3180 2462,3170 2462,3069 2491,3040 2606,3040 2618,3028 2618,2977 2606.44,2965.44 2415.56,2965.44 2387.74,2993.26 2387.74,3171.74
EMU_USB_5V0 on Top Layer "TOP_LAYER_EMU_USB_5V0_P169" (solid, remove dead copper, pour order 169): 2073,3149 2075,3151 2161,3151 2161,3207 2190,3236 2238,3236 2269,3205 2269,3128 2268,3128 2263,3123 2157,3123 2152,3128 2151.73,3127.73 2100.73,3127.73 2093,3120 2071,3120 2071,3148 2072,3149
EMU_USB_5V0 on Top Layer "TOP_LAYER_EMU_USB_5V0_P167" (solid, remove dead copper, pour order 167): 2081,3062 2241,3062 2257,3046 2257,2982 2242,2967 2187,2967 2162,2992 2162,3027 2159,3030 2158,3029 2070,3029 2070,3051 2072,3053
ISO_Pout_5V0 on Top Layer "TOP_LAYER_ISO_POUT_5V0_P170" (solid, remove dead copper, pour order 170): 3229.83,3332.29 3229.83,2973.27 3093.83,2973.27 3093.83,3332.29
NetD3_2 on Top Layer "TOP_LAYER_NETD3_2_P204" (solid, remove dead copper, pour order 204): 2920.83,3045.36 3093.83,3045.36 3093.83,2965.27 2920.83,2965.27
NetD4_2 on Top Layer "TOP_LAYER_NETD4_2_P210" (solid, remove dead copper, pour order 210): 2920.83,3188.27 3010.83,3188.27 3036.83,3221.85 3087.63,3221.85 3087.63,3334.27 2920.83,3334.27
EMU_3V3 on Top Layer "TOP_LAYER_EMU_3V3_P211" (solid, remove dead copper, pour order 211): 1978.78,2708.69 2162.81,2708.69 2162.81,2499.27 1978.78,2499.27
EMU_GND on Top Layer "Top Layer-EMU_GND" (solid, remove dead copper, pour order 238): 1791.87,2215.69 2152.71,2215.69 2232.5,2313.69 2572.87,2313.69 2572.87,2349.87 2537.87,2349.87 2537.87,2416.69 2373.83,2416.69 2373.83,2389.69 1791.87,2389.68
GND on Top Layer "TOP_LAYER_GND_P239" (solid, remove dead copper, pour order 239): 1719.72,2053.27 2676.54,2053.27 2919.72,2296.45 2919.72,3343.27 5870.72,3343.27 5870.72,1402.79 5870.72,1286.79 5827.18,1286.79 5808.28,1267.89 5808.28,1037.81 4833.7,1037.81 4813,1058.51 4813,1511.79 4165.69,1511.79 4169.72,1507.75 4169.72,1366.79 4194.72,1346.79 4233.69,1346.79 4233.69,1277.81 4233.69,1267.89 4233.59,1267.79 4056.77,1267.79 4056.77,1033.81 4055.79,1034.79 3025.72,1034.79 3025.72,1246.64 2992.1,1280.27 2948.2,1280.27 2919.72,1251.79 2919.72,1045.79 2015.72,1045.79 2010.72,1040.79 2010.72,1272.79 1838.72,1272.79 1825.69,1285.83 1825.69,1345.79 1887.72,1345.79 1921.88,1379.95 1921.88,1539.27 1719.72,1539.27
EMU_USB_5V0 on Power 4 "POWER_4_EMU_USB_5V0_P226" (solid, remove dead copper, pour order 226): 1744.33,3336.27 2621.83,3336.27 2621.83,3061.27 2540.83,2980.27 2231.89,2980.27 1969,2717.38 1969,2470 1935,2436 1766,2436 1746,2456 1746.09,2456.09 1746.09,3333.01
VDDIO_3V3 on Power 4 "POWER_4_VDDIO_3V3_P183" (solid, remove dead copper, pour order 183): 3051.62,2491.97 3110.91,2551.27 3453.71,2551.27 3474.36,2530.61 3474.36,2147 3472.37,2145.01 3407.6,2145.01 3407.6,2168.17 3402.07,2173.7 3401.32,2172.94 3371.71,2172.94 3371.71,2109.16 3398.65,2082.22 3420.92,2082.22 3420.92,2041.09 3450.34,2011.67 3529.24,2011.67 3535.77,2018.19 3535.77,2074.66 3566.81,2074.66 3566.81,2047.58 3699.24,2047.58 3712.83,2061.17 3712.83,2236.27 3754.05,2277.48 4002.52,2277.48 4017,2263 4017,2228.88 4036.96,2208.92 4105.52,2208.92 4127.95,2186.5 4129.5,2186.5 4129.5,1812.5 3932.87,1615.87 3080.13,1615.87 3051,1645 3051.62,1645.62
USB_5V0 on Power 4 "POWER_4_USB_5V0_P184" (solid, remove dead copper, pour order 184): 3493.24,3142.42 3704.33,3142.42 3718.84,3127.91 3716.76,3125.83 3716.76,2578.4 3690.78,2552.42 3493.24,2552.42 3475.24,2570.42 3476.23,2571.41 3476.23,3125.41
3V3 on Power 4 "POWER_4_3V3_P213" (solid, remove dead copper, pour order 213): 4162,2430 4133.23,2458.77 4133.23,2550.03 4241.24,2658.04 4241,2658.28 4241,2944.11 4271.94,2975.06 5146.04,2975.06 5404.83,2716.27 5404.83,2394.98 5401.27,2394.98 5383.05,2376.77 5188.23,2376.77 5135,2430 4151,2430
1V2 on Power 4 "POWER_4_1V2_P187" (solid, remove dead copper, pour order 187): 4109.83,2412.45 4134.84,2437.46 5127.54,2437.46 5170,2395 5170,1532.33 5152.67,1515 4994,1515 4972.58,1536.42 4972.58,1882.42 4813.15,2041.86 4811.86,2040.56 4144.6,2040.56 4128.24,2056.92 4128.24,2299.76 4109.83,2318.17
5V0 on Power 4 "POWER_4_5V0_P244" (solid, remove dead copper, pour order 244): 3290.63,3353.27 3292.82,3268 3292.82,3171.58 3156.51,3035.27 3062.29,2941.05 3064.02,2616.54 3128.11,2552.45 3486.33,2552.45 3486.33,3145.43 3719,3146.12 3719,2962.75 4032.83,2962.75 4032.83,3104.27 4065.9,3137.34 4209.9,3137.34 4213.27,2957.92 5170.57,2950.53 5403.83,2717.27 5403.83,2378.14 5165.94,2378.14 5153.94,1516.27 5866.83,1516.27 5866.83,3340.27 5853.83,3353.27
VDD_1V2 on Power 4 "POWER_4_VDD_1V2_P185" (solid, remove dead copper, pour order 185): 3365.91,2173.7 3402.07,2173.7 3402.07,2145.83 3478.47,2145.83 3478.47,2567.89 3715.24,2567.89 3715.24,2963.18 4018.71,2963.18 4018.71,3120.97 4046.43,3148.69 4204.73,3148.69 4232.49,3120.93 4232.49,2658.46 4124.48,2550.45 4124.48,2177 4020.38,2177 4020.38,2281.69 3753.96,2281.69 3712.83,2237 3712.83,2047.22 3558.64,2047.22 3558.64,2076.69 3532.92,2076.69 3532.92,2016.72 3433.75,2016.72 3433.75,2073.51 3367.06,2105.14
EMU_3V3 on Power 4 "POWER_4_EMU_3V3_P243" (solid, remove dead copper, pour order 243): 1737.81,3342.27 2773.69,3342.27 2773.69,2363.12 2613.83,2203.27 1732.87,2203.27
HSEC_5V0 on Power 4 "POWER_4_HSEC_5V0_P245" (solid, remove dead copper, pour order 245): 2921.53,3337.58 3326.38,3338.49 3326.38,3134.82 3225.37,3033.81 3155.05,3033.81 3081.86,2960.62 3076.44,2604.11 3116.18,2564.38 3057.58,2402.01 3057.58,1823.27 3057.58,1623.16 3569.85,1623.16 3694.81,1748.13 4050.7,1748.13 4125.05,1822.48 4125.05,2066.27 4796.39,2066.27 4977.83,1884.83 4977.83,1515.27 5133.83,1515.27 5852.53,1513.16 5860.83,1048.27 5873.83,1061.27 5687.83,1055.27 4835.47,1064.63 4830.83,1488.27 4812.09,1531.29 4180.61,1531.29 4229.53,1298.53 4050.7,1295.49 4053.83,1040.78 3148.32,1040.78 3180.83,1040.78 1738.83,1040.78 1738.83,2054.27 1813.83,2054.27 2675.53,2054.27 2921.53,2300.26
GND on Bottom "BOTTOM_GND_P235" (solid, remove dead copper, pour order 235): 1719.72,2053.27 2676.54,2053.27 2919.72,2296.45 2919.72,3343.27 5870.72,3343.27 5870.72,1402.79 5870.72,1286.79 5827.18,1286.79 5808.28,1267.89 5808.28,1037.81 4833.7,1037.81 4813,1058.51 4813,1511.79 4165.69,1511.79 4169.72,1507.75 4169.72,1366.79 4194.72,1346.79 4233.69,1346.79 4233.69,1277.81 4233.69,1267.89 4233.59,1267.79 4056.77,1267.79 4056.77,1033.81 4055.79,1034.79 3025.72,1034.79 3025.72,1246.64 2992.1,1280.27 2948.2,1280.27 2919.72,1251.79 2919.72,1045.79 2015.72,1045.79 2010.72,1040.79 2010.72,1272.79 1838.72,1272.79 1838.72,1345.79 1887.72,1345.79 1921.88,1379.95 1921.88,1539.27 1719.72,1539.27
NetC48_2 on Bottom "BOTTOM_NETC48_2_P203" (solid, remove dead copper, pour order 203): 5103.84,1777.69 5154.64,1777.69 5154.64,1765.59 5186.29,1733.95 5294.59,1733.95 5294.59,1678.24 5300.33,1674.64 5522.04,1674.87 5522.04,1715.48 5523.97,1717.4 5594.81,1717.4 5594.81,1679.48 5589.97,1674.64 5550.44,1674.64 5550.44,1587.99 5551.33,1587.1 5545.27,1581.04 5297.83,1581.04 5285.44,1593.44 5285.44,1637.86 5275.29,1648 5121,1648 5103.84,1665.16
